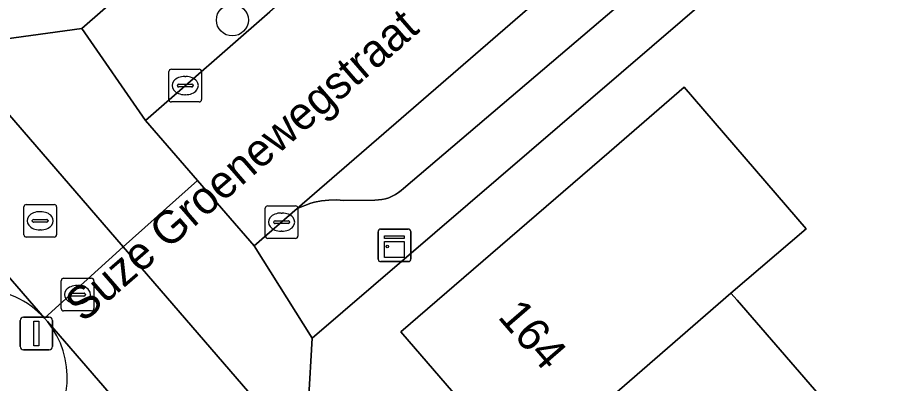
# Model space of a CAD drawing. Extents: x 160304 to 160955, y 383684 to 384161.
# Drawn here: x 160416.53 to 160443.23, y 383979.08 to 383990.29 of the extents above; entities that cross this region are included whole.
import ezdxf

# ---------------------------------------------------------------- set-up
doc = ezdxf.new("R2010")
doc.units = 0
for name, color, linetype in [('IMGEO_Boom', 7, 'Continuous'), ('IMGEO_Erf', 7, 'Continuous'), ('IMGEO_Kast', 7, 'Continuous'), ('IMGEO_Kolk', 7, 'Continuous'), ('IMGEO_Lichtmast', 7, 'Continuous'), ('IMGEO_Openbare_ruimte_label', 7, 'Continuous'), ('IMGEO_Pand', 7, 'Continuous'), ('IMGEO_Pand_nummerreeks', 7, 'Continuous'), ('IMGEO_Parkeervlak_open', 7, 'Continuous'), ('IMGEO_Rijbaan_lokaal_open', 7, 'Continuous'), ('IMGEO_Rioolput', 7, 'Continuous'), ('IMGEO_Voetpad_open', 7, 'Continuous')]:
    doc.layers.add(name, color=color, linetype=linetype)

msp = doc.modelspace()

# ---------------------------------------------------------------- linework, layer by layer
at = {"layer": 'IMGEO_Boom'}
msp.add_circle((160423.109, 383990.215), 0.489, dxfattribs=at)
at = {"layer": 'IMGEO_Erf'}
for points in [[(160415.887, 383989.594), (160418.503, 383989.954), (160429.993, 384000), (160434.935, 384004.073), (160433.617, 384005.604), (160436.338, 384007.945), (160429.882, 384015.395), (160427.166, 384013.044), (160425.937, 384014.464), (160424.585, 384016.025), (160427.301, 384018.376), (160422.435, 384023.998), (160419.719, 384021.647), (160418.52, 384023.031), (160417.138, 384024.628), (160419.854, 384026.979), (160415.02, 384032.564)], [(160456.376, 383974.841), (160452.604, 383979.153), (160455.89, 383982.028), (160452.212, 383986.286), (160449.864, 383989.004), (160451.404, 383990.334), (160449.988, 383991.923), (160447.265, 383989.57), (160443.455, 383993.98), (160442.593, 383995.12), (160425.555, 383980.472), (160425.435, 383978.53)], [(160432.006, 383976.333), (160428.265, 383980.663), (160434.642, 383986.171), (160436.938, 383988.154), (160440.676, 383983.825), (160438.37, 383981.85), (160438.564, 383981.631), (160442.108, 383977.528)]]:
    msp.add_lwpolyline(points, dxfattribs=at)
at = {"layer": 'IMGEO_Kast'}
for p, q in [((160427.646, 383983.815), (160428.487, 383983.815)), ((160428.487, 383983.815), (160427.646, 383983.815)), ((160427.571, 383982.89), (160427.571, 383983.731)), ((160427.571, 383983.731), (160427.571, 383982.89)), ((160428.571, 383983.74), (160428.571, 383982.899)), ((160428.571, 383982.899), (160428.571, 383983.74)), ((160428.496, 383982.815), (160427.655, 383982.815)), ((160427.655, 383982.815), (160428.496, 383982.815))]:
    msp.add_line(p, q, dxfattribs=at)
for points in [[(160427.766, 383983.605), (160428.366, 383983.605), (160428.366, 383983.52), (160427.766, 383983.52), (160427.766, 383983.605)], [(160427.766, 383983.43), (160428.366, 383983.43), (160428.366, 383982.941), (160427.766, 383982.941), (160427.766, 383983.43)]]:
    msp.add_lwpolyline(points, dxfattribs=at)
msp.add_circle((160427.85, 383983.279), 0.0377, dxfattribs=at)
for centre, start, end in [((160427.649, 383983.737), 92.4484, 184.2845), ((160427.649, 383983.737), 92.4484, 184.2845), ((160428.493, 383983.737), 2.4484, 94.2845), ((160428.493, 383983.737), 2.4484, 94.2845), ((160427.649, 383982.893), 182.4484, 274.2845), ((160427.649, 383982.893), 182.4484, 274.2845), ((160428.493, 383982.893), 272.4484, 4.2845), ((160428.493, 383982.893), 272.4484, 4.2845)]:
    msp.add_arc(centre, 0.0779, start, end, dxfattribs=at)
at = {"layer": 'IMGEO_Kolk'}
for p, q in [((160421.167, 383987.781), (160421.167, 383988.633)), ((160421.242, 383988.707), (160422.094, 383988.707)), ((160422.168, 383988.633), (160422.168, 383987.781)), ((160421.655, 383988.487), (160421.68, 383988.487)), ((160421.426, 383988.201), (160421.426, 383988.213)), ((160421.864, 383988.164), (160421.466, 383988.164)), ((160421.469, 383988.25), (160421.867, 383988.25)), ((160421.91, 383988.213), (160421.91, 383988.201)), ((160421.678, 383987.927), (160421.653, 383987.927)), ((160422.094, 383987.707), (160421.242, 383987.707)), ((160416.801, 383984.566), (160417.653, 383984.566)), ((160416.726, 383983.64), (160416.726, 383984.492)), ((160417.214, 383984.346), (160417.239, 383984.346)), ((160417.727, 383984.492), (160417.727, 383983.64)), ((160424.116, 383983.599), (160424.116, 383984.451)), ((160424.191, 383984.525), (160425.043, 383984.525)), ((160424.604, 383984.305), (160424.629, 383984.305)), ((160425.117, 383984.451), (160425.117, 383983.599)), ((160416.985, 383984.06), (160416.985, 383984.072)), ((160417.028, 383984.109), (160417.426, 383984.109)), ((160417.469, 383984.072), (160417.469, 383984.06)), ((160424.375, 383984.019), (160424.375, 383984.031)), ((160424.418, 383984.068), (160424.816, 383984.068)), ((160424.859, 383984.031), (160424.859, 383984.019)), ((160417.423, 383984.023), (160417.025, 383984.023)), ((160417.237, 383983.786), (160417.212, 383983.786)), ((160424.813, 383983.982), (160424.415, 383983.982)), ((160417.653, 383983.566), (160416.801, 383983.566)), ((160425.043, 383983.525), (160424.191, 383983.525)), ((160424.627, 383983.745), (160424.602, 383983.745))]:
    msp.add_line(p, q, dxfattribs=at)
for points in [[(160421.167, 383987.781), (160421.167, 383988.633)], [(160421.242, 383988.707), (160422.094, 383988.707)], [(160422.168, 383988.633), (160422.168, 383987.781)], [(160422.094, 383987.707), (160421.242, 383987.707)], [(160416.801, 383984.566), (160417.653, 383984.566)], [(160416.726, 383983.64), (160416.726, 383984.492)], [(160417.727, 383984.492), (160417.727, 383983.64)], [(160424.116, 383983.599), (160424.116, 383984.451)], [(160424.191, 383984.525), (160425.043, 383984.525)], [(160425.117, 383984.451), (160425.117, 383983.599)], [(160417.653, 383983.566), (160416.801, 383983.566)], [(160425.043, 383983.525), (160424.191, 383983.525)]]:
    msp.add_lwpolyline(points, dxfattribs=at)
for centre, radius, start, end in [((160421.244, 383988.631), 0.0765, 91.552, 178.448), ((160421.244, 383988.631), 0.0765, 91.552, 178.448), ((160422.092, 383988.631), 0.0765, 1.552, 88.448), ((160422.092, 383988.631), 0.0765, 1.552, 88.448), ((160421.466, 383988.21), 0.0403, 85.8775, 175.7526), ((160421.463, 383988.2), 0.0366, 178.938, 274.7102), ((160421.867, 383988.207), 0.043, 264.8664, 352.4533), ((160421.871, 383988.212), 0.0386, 1.7309, 96.639), ((160421.244, 383987.783), 0.0765, 181.552, 268.448), ((160421.244, 383987.783), 0.0765, 181.552, 268.448), ((160422.092, 383987.783), 0.0765, 271.552, 358.448), ((160422.092, 383987.783), 0.0765, 271.552, 358.448), ((160416.803, 383984.49), 0.0765, 91.552, 178.448), ((160416.803, 383984.49), 0.0765, 91.552, 178.448), ((160417.651, 383984.49), 0.0765, 1.552, 88.448), ((160417.651, 383984.49), 0.0765, 1.552, 88.448), ((160424.193, 383984.449), 0.0765, 91.552, 178.448), ((160424.193, 383984.449), 0.0765, 91.552, 178.448), ((160425.041, 383984.449), 0.0765, 1.552, 88.448), ((160425.041, 383984.449), 0.0765, 1.552, 88.448), ((160417.025, 383984.069), 0.0403, 85.8775, 175.7526), ((160417.022, 383984.059), 0.0366, 178.938, 274.7102), ((160417.426, 383984.066), 0.043, 264.8664, 352.4533), ((160417.43, 383984.071), 0.0386, 1.7309, 96.639), ((160424.415, 383984.028), 0.0403, 85.8775, 175.7526), ((160424.82, 383984.03), 0.0386, 1.7309, 96.639), ((160424.412, 383984.018), 0.0366, 178.938, 274.7102), ((160424.816, 383984.025), 0.043, 264.8664, 352.4533), ((160416.803, 383983.642), 0.0765, 181.552, 268.448), ((160416.803, 383983.642), 0.0765, 181.552, 268.448), ((160417.651, 383983.642), 0.0765, 271.552, 358.448), ((160417.651, 383983.642), 0.0765, 271.552, 358.448), ((160424.193, 383983.601), 0.0765, 181.552, 268.448), ((160424.193, 383983.601), 0.0765, 181.552, 268.448), ((160425.041, 383983.601), 0.0765, 271.552, 358.448), ((160425.041, 383983.601), 0.0765, 271.552, 358.448)]:
    msp.add_arc(centre, radius, start, end, dxfattribs=at)
for centre, major_axis, ratio, start_param, end_param in [((160421.654, 383988.207), (-0.387, 0.002), 0.722429, 4.712389, 7.853982), ((160421.679, 383988.207), (-0.39, 0.002), 0.717154, 1.570796, 4.712389), ((160417.213, 383984.066), (-0.387, 0.002), 0.722429, 4.712389, 7.853982), ((160417.238, 383984.066), (-0.39, 0.002), 0.717154, 1.570796, 4.712389), ((160424.603, 383984.025), (-0.387, 0.002), 0.722429, 4.712389, 7.853982), ((160424.628, 383984.025), (-0.39, 0.002), 0.717154, 1.570796, 4.712389)]:
    msp.add_ellipse(centre, major_axis=major_axis, ratio=ratio, start_param=start_param, end_param=end_param, dxfattribs=at)
at = {"layer": 'IMGEO_Lichtmast'}
for p, q in [((160416.712, 383981.116), (160417.502, 383981.116)), ((160417.502, 383981.116), (160416.712, 383981.116)), ((160416.612, 383980.216), (160416.612, 383981.016)), ((160416.612, 383981.016), (160416.612, 383980.216)), ((160417.602, 383981.016), (160417.602, 383980.216)), ((160417.602, 383980.216), (160417.602, 383981.016)), ((160417.502, 383980.116), (160416.712, 383980.116)), ((160416.712, 383980.116), (160417.502, 383980.116))]:
    msp.add_line(p, q, dxfattribs=at)
msp.add_lwpolyline([(160417.032, 383980.991), (160417.182, 383980.991), (160417.182, 383980.241), (160417.032, 383980.241), (160417.032, 383980.991)], dxfattribs=at)
for centre, start, end in [((160416.712, 383981.016), 90, 180), ((160416.712, 383981.016), 90, 180), ((160417.502, 383981.016), 0, 90), ((160417.502, 383981.016), 360, 90), ((160416.712, 383980.216), 180, 270), ((160416.712, 383980.216), 180, 270), ((160417.502, 383980.216), 270, 0), ((160417.502, 383980.216), 270, 0)]:
    msp.add_arc(centre, 0.1, start, end, dxfattribs=at)
at = {"layer": 'IMGEO_Pand'}
for points in [[(160440.676, 383983.825), (160436.938, 383988.154), (160434.642, 383986.171), (160428.265, 383980.663), (160432.006, 383976.333), (160438.37, 383981.85)], [(160438.564, 383981.631), (160438.37, 383981.85), (160432.006, 383976.333), (160435.741, 383972.009), (160442.108, 383977.528)]]:
    msp.add_lwpolyline(points, close=True, dxfattribs=at)
at = {"layer": 'IMGEO_Parkeervlak_open'}
for points in [[(160417.354, 383981.089), (160401.126, 383999.866)], [(160439.728, 383997.125), (160425.096, 383984.442), (160425.509, 383984.604), (160425.62, 383984.634), (160425.841, 383984.677), (160426.066, 383984.701), (160426.292, 383984.705), (160426.517, 383984.688), (160427.469, 383984.7), (160427.579, 383984.704), (160427.688, 383984.718), (160427.796, 383984.741), (160427.901, 383984.774), (160428.003, 383984.817), (160428.1, 383984.868), (160428.193, 383984.928), (160428.28, 383984.995), (160428.345, 383985.055), (160438.639, 383993.831)], [(160434.365, 383961.407), (160417.446, 383980.983)]]:
    msp.add_lwpolyline(points, dxfattribs=at)
for centre, start, end in [((160415.369, 383979.283), 42.2971, 135.319), ((160415.37, 383979.281), 312.6828, 39.3477)]:
    msp.add_arc(centre, 2.684, start, end, dxfattribs=at)
at = {"layer": 'IMGEO_Rijbaan_lokaal_open'}
msp.add_lwpolyline([(160484.061, 384038.186), (160473.972, 384034.203), (160473.91, 384034.061), (160473.654, 384033.596), (160473.358, 384033.154), (160473.024, 384032.741), (160472.654, 384032.36), (160472.252, 384032.013), (160471.504, 384031.385), (160443.247, 384006.975), (160442.642, 384006.44), (160439.545, 384003.767), (160435.187, 384000), (160424.255, 383990.462), (160420.449, 383987.142), (160422.038, 383985.305), (160423.775, 383983.297), (160425.096, 383984.442), (160439.728, 383997.125), (160440.231, 383997.562), (160443.044, 384000), (160446.077, 384002.618), (160446.417, 384002.912), (160475.034, 384027.614)], dxfattribs=at)
for points in [[(160405.328, 384000), (160399.379, 384006.883), (160396.906, 384004.745), (160401.01, 384000), (160401.126, 383999.866), (160417.354, 383981.089), (160419.771, 383983.265)], [(160417.354, 383981.089), (160417.446, 383980.983), (160434.365, 383961.407), (160438.655, 383956.443), (160441.098, 383958.554), (160419.771, 383983.265)]]:
    msp.add_lwpolyline(points, close=True, dxfattribs=at)
at = {"layer": 'IMGEO_Rioolput'}
for p, q in [((160417.869, 383981.38), (160417.869, 383982.232)), ((160417.944, 383982.306), (160418.796, 383982.306)), ((160418.87, 383982.232), (160418.87, 383981.38)), ((160418.357, 383982.086), (160418.382, 383982.086)), ((160418.128, 383981.8), (160418.128, 383981.812)), ((160418.566, 383981.763), (160418.168, 383981.763)), ((160418.171, 383981.849), (160418.569, 383981.849)), ((160418.612, 383981.812), (160418.612, 383981.8)), ((160418.38, 383981.526), (160418.355, 383981.526)), ((160418.796, 383981.306), (160417.944, 383981.306))]:
    msp.add_line(p, q, dxfattribs=at)
for points in [[(160417.869, 383981.38), (160417.869, 383982.232)], [(160417.944, 383982.306), (160418.796, 383982.306)], [(160418.87, 383982.232), (160418.87, 383981.38)], [(160418.796, 383981.306), (160417.944, 383981.306)]]:
    msp.add_lwpolyline(points, dxfattribs=at)
for centre, radius, start, end in [((160417.946, 383982.23), 0.0765, 91.552, 178.448), ((160417.946, 383982.23), 0.0765, 91.552, 178.448), ((160418.794, 383982.23), 0.0765, 1.552, 88.448), ((160418.794, 383982.23), 0.0765, 1.552, 88.448), ((160418.168, 383981.809), 0.0403, 85.8775, 175.7526), ((160418.165, 383981.799), 0.0366, 178.938, 274.7102), ((160418.569, 383981.806), 0.043, 264.8664, 352.4533), ((160418.573, 383981.811), 0.0386, 1.7309, 96.639), ((160417.946, 383981.382), 0.0765, 181.552, 268.448), ((160417.946, 383981.382), 0.0765, 181.552, 268.448), ((160418.794, 383981.382), 0.0765, 271.552, 358.448), ((160418.794, 383981.382), 0.0765, 271.552, 358.448)]:
    msp.add_arc(centre, radius, start, end, dxfattribs=at)
for centre, major_axis, ratio, start_param, end_param in [((160418.356, 383981.806), (-0.387, 0.002), 0.722429, 4.712389, 7.853982), ((160418.381, 383981.806), (-0.39, 0.002), 0.717154, 1.570796, 4.712389)]:
    msp.add_ellipse(centre, major_axis=major_axis, ratio=ratio, start_param=start_param, end_param=end_param, dxfattribs=at)
at = {"layer": 'IMGEO_Voetpad_open'}
for points in [[(160364.754, 384046.943), (160397.588, 384008.955), (160399.379, 384006.883), (160405.328, 384000), (160419.771, 383983.265), (160422.038, 383985.305), (160420.449, 383987.142), (160418.503, 383989.954), (160415.887, 383989.594), (160406.925, 384000), (160366.633, 384046.782)], [(160460.261, 384032.534), (160463.456, 384028.84), (160440.174, 384008.722), (160437.655, 384006.413), (160434.935, 384004.073), (160429.993, 384000), (160418.503, 383989.954), (160420.449, 383987.142), (160424.255, 383990.462)], [(160438.639, 383993.831), (160428.345, 383985.055), (160428.28, 383984.995), (160428.193, 383984.928), (160428.1, 383984.868), (160428.003, 383984.817), (160427.901, 383984.774), (160427.796, 383984.741), (160427.688, 383984.718), (160427.579, 383984.704), (160427.469, 383984.7), (160426.517, 383984.688), (160426.292, 383984.705), (160426.066, 383984.701), (160425.841, 383984.677), (160425.62, 383984.634), (160425.509, 383984.604), (160425.096, 383984.442), (160423.775, 383983.297), (160425.555, 383980.472), (160442.593, 383995.12)], [(160425.435, 383978.53), (160425.555, 383980.472), (160423.775, 383983.297), (160422.038, 383985.305), (160419.771, 383983.265), (160441.098, 383958.554)], [(160417.446, 383980.983), (160417.354, 383981.089)]]:
    msp.add_lwpolyline(points, dxfattribs=at)
for centre, start, end in [((160415.369, 383979.283), 42.2971, 135.319), ((160415.37, 383979.281), 312.6828, 39.3477)]:
    msp.add_arc(centre, 2.684, start, end, dxfattribs=at)

# ---------------------------------------------------------------- texts
at = {"layer": 'IMGEO_Openbare_ruimte_label'}
msp.add_text('Suze Groenewegstraat', height=1, rotation=40.9057, dxfattribs=at).set_placement((160418.543, 383980.926))
at = {"layer": 'IMGEO_Pand_nummerreeks'}
msp.add_text('164', height=1, rotation=310.823, dxfattribs=at).set_placement((160431.205, 383981.114))

doc.saveas('drawing.dxf')
